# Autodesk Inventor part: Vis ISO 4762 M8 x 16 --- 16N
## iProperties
Created: 2011-01
Part Number: Vis ISO 4762 M8 x 16 --- 16N
Document SubType Name: Modeling
Designer: eric
Density: 1 g/cm^3
Mass: 1.71416 g
Surface Area: 10.6117 cm^2
Volume: 1.71416 cm^3
Author: eric
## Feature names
1. Base1
